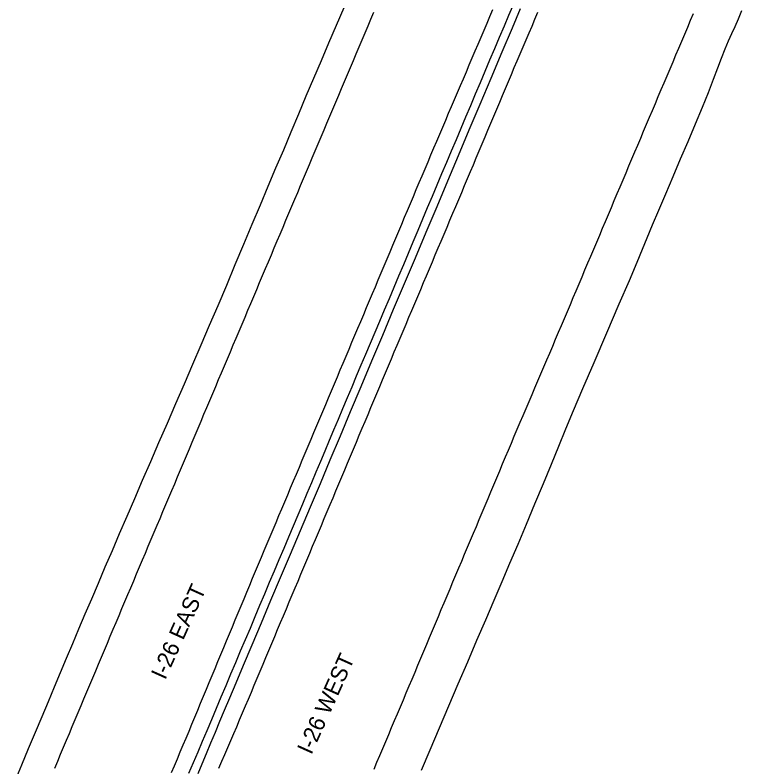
# Model space of a CAD drawing. Extents: x 1948091 to 1975253, y 787267 to 823306.
# Drawn here: x 1966815.4 to 1967056.6, y 792679.5 to 792929 of the extents above; entities that cross this region are included whole.
import ezdxf

# ---------------------------------------------------------------- set-up
doc = ezdxf.new("R2010")
doc.units = 0
for name, color, linetype in [('RD_EX_Pavement_Markings', 7, 'Continuous'), ('RD_EX_Road', 7, 'Continuous'), ('RD_TX_RoadID', 7, 'Continuous')]:
    doc.layers.add(name, color=color, linetype=linetype)

msp = doc.modelspace()

# ---------------------------------------------------------------- linework, layer by layer
at = {"layer": 'RD_EX_Pavement_Markings'}
for points in [[(1966934.4, 792929.87), (1966933.43, 792927.57), (1966932.45, 792925.27), (1966931.48, 792922.97), (1966930.51, 792920.67), (1966929.53, 792918.37), (1966928.56, 792916.07), (1966927.58, 792913.77), (1966926.61, 792911.47), (1966925.64, 792909.17), (1966924.66, 792906.87), (1966923.69, 792904.57), (1966922.71, 792902.27), (1966921.74, 792899.97), (1966920.77, 792897.67), (1966919.79, 792895.36), (1966918.82, 792893.06), (1966917.85, 792890.76), (1966916.88, 792888.46), (1966915.9, 792886.16), (1966914.93, 792883.86), (1966913.96, 792881.56), (1966912.99, 792879.26), (1966912.02, 792876.96), (1966911.05, 792874.65), (1966910.08, 792872.35), (1966909.11, 792870.05), (1966908.14, 792867.75), (1966907.16, 792865.45), (1966906.19, 792863.15), (1966905.22, 792860.85), (1966904.25, 792858.54), (1966903.28, 792856.24), (1966902.31, 792853.94), (1966901.34, 792851.64), (1966900.37, 792849.34), (1966899.4, 792847.04), (1966898.42, 792844.74), (1966897.45, 792842.44), (1966896.48, 792840.13), (1966895.51, 792837.83), (1966894.54, 792835.53), (1966893.57, 792833.23), (1966892.6, 792830.93), (1966891.63, 792828.63), (1966890.66, 792826.33), (1966889.69, 792824.02), (1966888.71, 792821.72), (1966887.74, 792819.42), (1966886.77, 792817.12), (1966885.8, 792814.82), (1966884.83, 792812.52), (1966883.86, 792810.22), (1966882.88, 792807.92), (1966881.91, 792805.62), (1966880.94, 792803.31), (1966879.97, 792801.01), (1966878.99, 792798.71), (1966878.02, 792796.41), (1966877.05, 792794.11), (1966876.08, 792791.81), (1966875.11, 792789.51), (1966874.13, 792787.21), (1966873.16, 792784.91), (1966872.19, 792782.61), (1966871.22, 792780.31), (1966870.24, 792778), (1966869.27, 792775.7), (1966868.3, 792773.4), (1966867.33, 792771.1), (1966866.36, 792768.8), (1966865.38, 792766.5), (1966864.41, 792764.2), (1966863.44, 792761.9), (1966862.47, 792759.6), (1966861.49, 792757.3), (1966860.52, 792755), (1966859.55, 792752.7), (1966858.58, 792750.39), (1966857.61, 792748.09), (1966856.63, 792745.79), (1966855.66, 792743.49), (1966854.69, 792741.19), (1966853.72, 792738.89), (1966852.74, 792736.59), (1966851.77, 792734.29), (1966850.8, 792731.99), (1966849.83, 792729.69), (1966848.86, 792727.38), (1966847.89, 792725.08), (1966846.92, 792722.78), (1966845.95, 792720.48), (1966844.98, 792718.18), (1966844.02, 792715.87), (1966843.05, 792713.57), (1966842.08, 792711.27), (1966841.11, 792708.97), (1966840.14, 792706.67), (1966839.17, 792704.37), (1966838.2, 792702.06), (1966837.23, 792699.76), (1966836.26, 792697.46), (1966835.29, 792695.16), (1966834.32, 792692.86), (1966833.35, 792690.55), (1966832.38, 792688.25), (1966831.41, 792685.95), (1966830.44, 792683.65), (1966829.47, 792681.35), (1966828.5, 792679.05)], [(1966973.88, 792930.75), (1966972.91, 792928.45), (1966971.93, 792926.16), (1966970.95, 792923.86), (1966969.97, 792921.56), (1966968.99, 792919.26), (1966968.01, 792916.96), (1966967.03, 792914.67), (1966966.05, 792912.37), (1966965.07, 792910.07), (1966964.09, 792907.77), (1966963.11, 792905.47), (1966962.13, 792903.17), (1966961.16, 792900.88), (1966960.18, 792898.58), (1966959.2, 792896.28), (1966958.22, 792893.98), (1966957.24, 792891.68), (1966956.26, 792889.39), (1966955.28, 792887.09), (1966954.3, 792884.79), (1966953.32, 792882.49), (1966952.35, 792880.19), (1966951.38, 792877.89), (1966950.41, 792875.59), (1966949.44, 792873.28), (1966948.47, 792870.98), (1966947.5, 792868.68), (1966946.53, 792866.38), (1966945.56, 792864.08), (1966944.59, 792861.78), (1966943.62, 792859.47), (1966942.65, 792857.17), (1966941.68, 792854.87), (1966940.71, 792852.57), (1966939.74, 792850.27), (1966938.77, 792847.97), (1966937.8, 792845.66), (1966936.83, 792843.36), (1966935.86, 792841.06), (1966934.89, 792838.76), (1966933.92, 792836.46), (1966932.95, 792834.16), (1966931.98, 792831.85), (1966931.01, 792829.55), (1966930.04, 792827.25), (1966929.06, 792824.95), (1966928.09, 792822.65), (1966927.12, 792820.34), (1966926.15, 792818.04), (1966925.18, 792815.74), (1966924.21, 792813.44), (1966923.24, 792811.14), (1966922.27, 792808.83), (1966921.3, 792806.53), (1966920.34, 792804.23), (1966919.37, 792801.93), (1966918.4, 792799.63), (1966917.43, 792797.32), (1966916.46, 792795.02), (1966915.49, 792792.72), (1966914.52, 792790.42), (1966913.55, 792788.12), (1966912.58, 792785.81), (1966911.61, 792783.51), (1966910.64, 792781.21), (1966909.67, 792778.91), (1966908.7, 792776.6), (1966907.73, 792774.3), (1966906.76, 792772), (1966905.8, 792769.7), (1966904.83, 792767.4), (1966903.86, 792765.09), (1966902.89, 792762.79), (1966901.92, 792760.49), (1966900.95, 792758.19), (1966899.98, 792755.88), (1966899.01, 792753.58), (1966898.04, 792751.28), (1966897.07, 792748.98), (1966896.1, 792746.67), (1966895.13, 792744.37), (1966894.17, 792742.07), (1966893.22, 792739.76), (1966892.26, 792737.45), (1966891.3, 792735.15), (1966890.34, 792732.84), (1966889.38, 792730.53), (1966888.42, 792728.23), (1966887.46, 792725.92), (1966886.5, 792723.62), (1966885.54, 792721.31), (1966884.58, 792719), (1966883.62, 792716.7), (1966882.66, 792714.39), (1966881.7, 792712.08), (1966880.74, 792709.78), (1966879.78, 792707.47), (1966878.82, 792705.17), (1966877.86, 792702.86), (1966876.9, 792700.55), (1966875.94, 792698.25), (1966874.99, 792695.94), (1966874.03, 792693.64), (1966873.07, 792691.33), (1966872.11, 792689.02), (1966871.13, 792686.72), (1966870.16, 792684.42), (1966869.19, 792682.12), (1966868.21, 792679.82), (1966867.24, 792677.52)], [(1966988.83, 792929.83), (1966987.85, 792927.53), (1966986.87, 792925.24), (1966985.88, 792922.94), (1966984.9, 792920.64), (1966983.91, 792918.35), (1966982.93, 792916.05), (1966981.96, 792913.75), (1966980.99, 792911.45), (1966980.02, 792909.15), (1966979.05, 792906.85), (1966978.08, 792904.54), (1966977.11, 792902.24), (1966976.13, 792899.94), (1966975.16, 792897.64), (1966974.19, 792895.34), (1966973.22, 792893.04), (1966972.25, 792890.73), (1966971.28, 792888.43), (1966970.31, 792886.13), (1966969.34, 792883.83), (1966968.37, 792881.53), (1966967.4, 792879.23), (1966966.43, 792876.93), (1966965.46, 792874.62), (1966964.49, 792872.32), (1966963.52, 792870.02), (1966962.55, 792867.72), (1966961.57, 792865.42), (1966960.6, 792863.12), (1966959.63, 792860.82), (1966958.66, 792858.51), (1966957.69, 792856.21), (1966956.72, 792853.91), (1966955.75, 792851.61), (1966954.77, 792849.31), (1966953.8, 792847.01), (1966952.83, 792844.71), (1966951.86, 792842.41), (1966950.89, 792840.11), (1966949.92, 792837.81), (1966948.94, 792835.5), (1966947.97, 792833.2), (1966947, 792830.9), (1966946.03, 792828.6), (1966945.06, 792826.3), (1966944.09, 792824), (1966943.11, 792821.7), (1966942.14, 792819.4), (1966941.17, 792817.09), (1966940.2, 792814.79), (1966939.23, 792812.49), (1966938.25, 792810.19), (1966937.28, 792807.89), (1966936.32, 792805.59), (1966935.35, 792803.28), (1966934.38, 792800.98), (1966933.41, 792798.68), (1966932.45, 792796.38), (1966931.48, 792794.07), (1966930.51, 792791.77), (1966929.55, 792789.47), (1966928.58, 792787.16), (1966927.61, 792784.86), (1966926.64, 792782.56), (1966925.68, 792780.25), (1966924.71, 792777.95), (1966923.74, 792775.65), (1966922.78, 792773.34), (1966921.81, 792771.04), (1966920.84, 792768.74), (1966919.88, 792766.44), (1966918.91, 792764.13), (1966917.94, 792761.83), (1966916.97, 792759.53), (1966916.01, 792757.22), (1966915.04, 792754.92), (1966914.07, 792752.62), (1966913.11, 792750.32), (1966912.14, 792748.01), (1966911.17, 792745.71), (1966910.2, 792743.41), (1966909.23, 792741.11), (1966908.26, 792738.8), (1966907.3, 792736.5), (1966906.33, 792734.2), (1966905.36, 792731.9), (1966904.39, 792729.59), (1966903.42, 792727.29), (1966902.46, 792724.99), (1966901.49, 792722.69), (1966900.52, 792720.38), (1966899.55, 792718.08), (1966898.58, 792715.78), (1966897.61, 792713.48), (1966896.65, 792711.17), (1966895.68, 792708.87), (1966894.71, 792706.57), (1966893.74, 792704.27), (1966892.77, 792701.96), (1966891.81, 792699.66), (1966890.83, 792697.36), (1966889.85, 792695.06), (1966888.87, 792692.77), (1966887.89, 792690.47), (1966886.91, 792688.17), (1966885.94, 792685.87), (1966884.96, 792683.57), (1966883.98, 792681.28), (1966883, 792678.98)], [(1966934.56, 792678.78), (1966935.53, 792681.08), (1966936.5, 792683.38), (1966937.48, 792685.68), (1966938.45, 792687.98), (1966939.42, 792690.29), (1966940.4, 792692.59), (1966941.37, 792694.89), (1966942.34, 792697.19), (1966943.32, 792699.49), (1966944.29, 792701.79), (1966945.26, 792704.09), (1966946.23, 792706.39), (1966947.2, 792708.69), (1966948.17, 792711), (1966949.13, 792713.3), (1966950.1, 792715.6), (1966951.07, 792717.9), (1966952.04, 792720.21), (1966953.01, 792722.51), (1966953.97, 792724.81), (1966954.94, 792727.11), (1966955.91, 792729.42), (1966956.88, 792731.72), (1966957.84, 792734.02), (1966958.81, 792736.32), (1966959.78, 792738.63), (1966960.75, 792740.93), (1966961.72, 792743.23), (1966962.68, 792745.54), (1966963.65, 792747.84), (1966964.62, 792750.14), (1966965.59, 792752.44), (1966966.56, 792754.74), (1966967.53, 792757.05), (1966968.5, 792759.35), (1966969.46, 792761.65), (1966970.43, 792763.95), (1966971.4, 792766.26), (1966972.37, 792768.56), (1966973.34, 792770.86), (1966974.31, 792773.16), (1966975.28, 792775.46), (1966976.24, 792777.77), (1966977.21, 792780.07), (1966978.18, 792782.37), (1966979.15, 792784.67), (1966980.12, 792786.98), (1966981.1, 792789.27), (1966982.08, 792791.57), (1966983.06, 792793.87), (1966984.04, 792796.17), (1966985.02, 792798.47), (1966986, 792800.76), (1966986.97, 792803.06), (1966987.95, 792805.36), (1966988.93, 792807.66), (1966989.91, 792809.96), (1966990.89, 792812.26), (1966991.87, 792814.55), (1966992.85, 792816.85), (1966993.83, 792819.15), (1966994.8, 792821.45), (1966995.78, 792823.75), (1966996.76, 792826.04), (1966997.74, 792828.34), (1966998.71, 792830.64), (1966999.69, 792832.94), (1967000.66, 792835.24), (1967001.63, 792837.54), (1967002.6, 792839.85), (1967003.58, 792842.15), (1967004.55, 792844.45), (1967005.52, 792846.75), (1967006.5, 792849.05), (1967007.47, 792851.35), (1967008.44, 792853.65), (1967009.42, 792855.95), (1967010.39, 792858.25), (1967011.36, 792860.55), (1967012.33, 792862.85), (1967013.31, 792865.15), (1967014.28, 792867.45), (1967015.25, 792869.75), (1967016.23, 792872.05), (1967017.2, 792874.35), (1967018.17, 792876.65), (1967019.15, 792878.95), (1967020.12, 792881.25), (1967021.09, 792883.56), (1967022.07, 792885.86), (1967023.04, 792888.16), (1967024.01, 792890.46), (1967024.99, 792892.76), (1967025.96, 792895.06), (1967026.93, 792897.36), (1967027.91, 792899.66), (1967028.88, 792901.96), (1967029.85, 792904.26), (1967030.83, 792906.56), (1967031.8, 792908.86), (1967032.77, 792911.16), (1967033.75, 792913.46), (1967034.72, 792915.76), (1967035.7, 792918.06), (1967036.67, 792920.36), (1967037.65, 792922.66), (1967038.62, 792924.96), (1967039.6, 792927.26), (1967040.57, 792929.56)]]:
    msp.add_lwpolyline(points, dxfattribs=at)
at = {"layer": 'RD_EX_Road'}
for points in [[(1966873.15, 792677.41), (1966874.68, 792681.01), (1966876.2, 792684.58), (1966877.69, 792688.12), (1966879.2, 792691.67), (1966880.73, 792695.3), (1966882.29, 792699), (1966883.88, 792702.77), (1966885.48, 792706.58), (1966887.09, 792710.39), (1966888.69, 792714.2), (1966890.3, 792718.01), (1966891.9, 792721.82), (1966893.51, 792725.62), (1966895.11, 792729.42), (1966896.71, 792733.22), (1966898.31, 792737.01), (1966899.91, 792740.8), (1966901.51, 792744.59), (1966903.11, 792748.37), (1966904.69, 792752.14), (1966906.27, 792755.86), (1966907.82, 792759.55), (1966909.37, 792763.21), (1966910.89, 792766.82), (1966912.41, 792770.4), (1966913.9, 792773.95), (1966915.38, 792777.46), (1966916.85, 792780.95), (1966918.32, 792784.44), (1966919.79, 792787.93), (1966921.26, 792791.43), (1966922.73, 792794.94), (1966924.22, 792798.48), (1966925.73, 792802.05), (1966927.25, 792805.65), (1966928.78, 792809.27), (1966930.32, 792812.89), (1966931.85, 792816.5), (1966933.38, 792820.12), (1966934.93, 792823.76), (1966936.48, 792827.43), (1966938.05, 792831.15), (1966939.63, 792834.9), (1966941.22, 792838.68), (1966942.81, 792842.46), (1966944.39, 792846.23), (1966945.98, 792850.02), (1966947.56, 792853.8), (1966949.15, 792857.57), (1966950.74, 792861.34), (1966952.33, 792865.11), (1966953.92, 792868.87), (1966955.51, 792872.63), (1966957.1, 792876.4), (1966958.69, 792880.16), (1966960.28, 792883.93), (1966961.87, 792887.7), (1966963.46, 792891.48), (1966965.05, 792895.25), (1966966.64, 792899.03), (1966968.23, 792902.81), (1966969.83, 792906.58), (1966971.42, 792910.35), (1966973.01, 792914.12), (1966974.61, 792917.89), (1966976.21, 792921.67), (1966977.81, 792925.44), (1966979.3, 792928.96), (1966980.57, 792931.97)], [(1966815.44, 792674.92), (1966817.67, 792680.24), (1966819.95, 792685.66), (1966822.21, 792691.04), (1966824.39, 792696.24), (1966826.5, 792701.26), (1966828.53, 792706.1), (1966830.52, 792710.87), (1966832.54, 792715.66), (1966834.57, 792720.49), (1966836.63, 792725.34), (1966838.72, 792730.28), (1966840.88, 792735.35), (1966843.1, 792740.55), (1966845.39, 792745.89), (1966847.74, 792751.37), (1966850.15, 792756.98), (1966852.63, 792762.73), (1966855.17, 792768.62), (1966857.78, 792774.65), (1966860.45, 792780.83), (1966863.19, 792787.15), (1966865.99, 792793.62), (1966868.82, 792800.14), (1966871.63, 792806.65), (1966874.43, 792813.12), (1966877.22, 792819.58), (1966880.01, 792826.07), (1966882.83, 792832.68), (1966885.67, 792839.4), (1966888.53, 792846.22), (1966891.37, 792853.01), (1966894.13, 792859.6), (1966896.83, 792865.99), (1966899.45, 792872.18), (1966902.02, 792878.26), (1966904.57, 792884.29), (1966907.09, 792890.28), (1966909.59, 792896.23), (1966912.08, 792902.14), (1966914.58, 792908.03), (1966917.08, 792913.9), (1966919.59, 792919.74), (1966922.1, 792925.59), (1966924.61, 792931.51)], [(1966876.17, 792677.38), (1966877.52, 792680.58), (1966878.95, 792683.99), (1966880.42, 792687.52), (1966881.92, 792691.09), (1966883.44, 792694.7), (1966884.97, 792698.34), (1966886.71, 792702.45), (1966888.81, 792707.44), (1966891.29, 792713.32), (1966894.14, 792720.09), (1966897.21, 792727.38), (1966900.35, 792734.82), (1966903.56, 792742.41), (1966906.84, 792750.15), (1966910.15, 792757.96), (1966913.46, 792765.79), (1966916.75, 792773.61), (1966920.04, 792781.44), (1966923.37, 792789.37), (1966926.77, 792797.48), (1966930.26, 792805.77), (1966933.82, 792814.24), (1966937.43, 792822.8), (1966941.04, 792831.36), (1966944.65, 792839.91), (1966948.27, 792848.46), (1966951.88, 792857), (1966955.46, 792865.51), (1966959.04, 792873.99), (1966962.59, 792882.44), (1966966.16, 792890.91), (1966969.76, 792899.46), (1966973.4, 792908.09), (1966977.08, 792916.8), (1966980.44, 792924.76), (1966983.15, 792931.16)], [(1966950.34, 792678.45), (1966953.19, 792685.18), (1966956.29, 792692.5), (1966959.4, 792699.82), (1966962.52, 792707.12), (1966965.65, 792714.42), (1966968.71, 792721.55), (1966971.63, 792728.36), (1966974.41, 792734.84), (1966977.05, 792741.01), (1966979.65, 792747.13), (1966982.34, 792753.48), (1966985.1, 792760.05), (1966987.95, 792766.86), (1966990.75, 792773.6), (1966993.4, 792779.98), (1966995.89, 792786), (1966998.23, 792791.66), (1967000.77, 792797.76), (1967003.88, 792805.11), (1967007.55, 792813.7), (1967011.8, 792823.54), (1967015.93, 792833.13), (1967019.29, 792840.96), (1967021.86, 792847.03), (1967023.64, 792851.35), (1967025.17, 792855.07), (1967026.97, 792859.37), (1967029.03, 792864.25), (1967031.36, 792869.71), (1967033.82, 792875.47), (1967036.28, 792881.25), (1967038.73, 792887.04), (1967041.19, 792892.86), (1967043.49, 792898.39), (1967045.49, 792903.33), (1967047.2, 792907.68), (1967048.62, 792911.43), (1967049.86, 792914.74), (1967051.05, 792917.74), (1967052.2, 792920.44), (1967053.3, 792922.84), (1967054.38, 792925.19), (1967055.5, 792927.75), (1967056.63, 792930.52)]]:
    msp.add_lwpolyline(points, dxfattribs=at)

# ---------------------------------------------------------------- texts
at = {"layer": 'RD_TX_RoadID'}
for s, p in [('I-26 EAST', (1966865.27, 792708.16)), ('I-26 WEST', (1966913.75, 792683.34))]:
    msp.add_text(s, height=5.4, rotation=65.7673, dxfattribs=at).set_placement(p)

doc.saveas('drawing.dxf')
